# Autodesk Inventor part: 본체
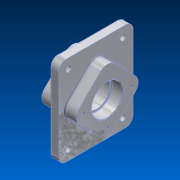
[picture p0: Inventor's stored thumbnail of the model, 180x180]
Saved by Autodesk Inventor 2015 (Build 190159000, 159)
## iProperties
Created: 2026-07
Part Number: 본체
Material: 알루미늄 6061
Document SubType Name: Modeling
Designer: user
Density: 2.7 g/cm^3
Appearance: 알루미늄 - 평지
Mass: 2132.41 g
Surface Area: 955.114 cm^2
Volume: 789.782 cm^3
Author: user
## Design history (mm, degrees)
sketch "스케치2"
  geometry: L1 (-75, 90)-(75, 90); L2 (75, 90)-(75, -90); L3 (75, -90)-(-75, -90); L4 (-75, -90)-(-75, 90); L5 (-75, 90)-(75, -90); L6 (75, 90)-(-75, -90); 1 further point
  constraints: 12 end point, 2 midpoint, 2 parallel, 1 horizontal, 1 perpendicular
  dimensions: "d0" = 150 distance of L2.end L3.end; "d1" = 180 distance of L1.end L2.end
extrude "돌출1" new body sketch "스케치2" stored distance "d2" = 18; taper "d3" = 0 deg
sketch "스케치3"
  geometry: L1 (70.711, 0)-(0, -70.711); L2 (0, -70.711)-(-70.711, 0); L3 (-70.711, 0)-(0, 70.711); L4 (0, 70.711)-(70.711, 0); 2 further points
  constraints: 8 end point, 1 coincident, 9 other
  dimensions: "d4" = 100 distance of L2.end L3.end
extrude "돌출2" join sketch "스케치3" distance "d5" = 23; taper "d6" = 0 deg
sketch "스케치4"
  geometry: L1 (-70.711, 0)-(0, 70.711); L2 (0, 70.711)-(70.711, 0); L3 (70.711, 0)-(0, -70.711); L4 (0, -70.711)-(-70.711, 0); 2 further points
  constraints: 8 end point, 1 coincident, 9 other
  dimensions: "d7" = 100 distance of L3.end L1.start
extrude "돌출3" join sketch "스케치4" distance "d8" = 29; taper "d9" = 0 deg
sketch "스케치5"
  geometry: L1 (0, 70.711)-(70.711, 0) reference; L2 (70.711, 0)-(0, -70.711) reference; L3 (0, -70.711)-(-70.711, 0) reference; L4 (-70.711, 0)-(0, 70.711) reference; L5 (-90, 75)-(90, 75) reference; L6 (90, 75)-(90, -75) reference; L7 (90, -75)-(-90, -75) reference; L8 (-90, -75)-(-90, 75) reference; C1 r 11 at (70, -55); C2 r 11 at (-70, -55); C3 r 11 at (70, 55); C4 r 11 at (-70, 55); 1 further point
  constraints: 4 centre point, 2 horizontal alignment, 1 vertical alignment
  dimensions: "d10" = 11 radius of C1; "d11" = 11 radius of C2; "d12" = 140 distance of C2.centre C1.centre; "d13" = 11 radius of C3; "d14" = 11 radius of C4; "d15" = 140 distance of C4.centre C3.centre; "d16" = 110 distance of C1.centre C3.centre; "d17" = 55 vertical distance of point (0, 0) C3.centre; "d18" = 70 horizontal distance of C4.centre point (0, 0)
extrude "돌출4" join sketch "스케치5" distance "d19" = 5; taper "d20" = 0 deg
hole "구멍1" diameter "d23" = 11; stored, may be unused: countersink angle "d27" = 90 deg, drill point angle "d29" = 0 deg; dims "d21" = 10, "d22" = 10, "d24" = 6, "d25" = 4, "d26" = 2, "d28" = 8
sketch "스케치6"
  geometry: C1 r 31 at (0, 0); 1 further point
  constraints: 1 centre point, 1 coincident
  dimensions: "d36" = 31 radius of C1
extrude "돌출5" cut sketch "스케치6" distance "d37" = 22; taper "d38" = 0 deg
sketch "스케치7"
  geometry: C1 r 31 at (0, 0); 1 further point
  constraints: 1 centre point, 1 coincident
  dimensions: "d39" = 31 radius of C1
extrude "돌출6" cut sketch "스케치7" distance "d40" = 22; taper "d41" = 0 deg
hole "구멍2" diameter "d44" = 54; stored, may be unused: countersink angle "d48" = 90 deg, drill point angle "d50" = 0 deg; dims "d42" = 10, "d43" = 10, "d45" = 6, "d46" = 4, "d47" = 2, "d49" = 8
sketch "스케치8"
  geometry: L1 (0, 0)-(-48, 0)
  constraints: 2 end point, 1 horizontal
  dimensions: "d51" = 48 distance of L1.start L1.end
hole "구멍3" sketch "스케치8" at (-48, 0) diameter "d52" = 4.917; stored, may be unused: countersink angle "d56" = 90 deg, drill point angle "d58" = 118 deg; dims "d53" = 10, "d54" = 4, "d55" = 2, "d57" = 13
sketch "스케치9"
  geometry: L1 (0, 0)-(48, 0); C1 r 2.458 at (48, 0) reference
  constraints: 2 end point, 1 horizontal
  dimensions: "d62" = 48 distance of L1.start L1.end (derived)
hole "구멍4" sketch "스케치9" at (48, 0) diameter "d63" = 4.917; stored, may be unused: countersink angle "d67" = 90 deg, drill point angle "d69" = 118 deg; dims "d64" = 10, "d65" = 4, "d66" = 2, "d68" = 13
sketch "스케치10"
  geometry: L1 (90, -75)-(90, 75) reference; 2 further points
  constraints: 1 horizontal alignment, 1 other
  dimensions: "d73" = 15 distance from line of point (75, 0) L1
feature "엠보싱1" sketch "스케치10" dims "d0" = 150, "d1" = 180, "d7" = 100, "d74" = 0.5, "d75" = 0
chamfer "모따기1" distance "d76" = 1; stored, may be unused: second distance "d77" = 2, angle "d78" = 45 deg
fillet "모깎기1" dims "d79" = 15
fillet "모깎기2" dims "d80" = 3
fillet "모깎기3" dims "d81" = 20
fillet "모깎기4" dims "d82" = 20
fillet "모깎기5" dims "d83" = 3
fillet "모깎기6" dims "d84" = 3
fillet "모깎기7" dims "d85" = 3
fillet "모깎기8" dims "d86" = 1
node "솔리드1"
pattern_linear "직사각형 패턴1" dims "d32" = 110
pattern_circular "원형 패턴1" dims angle "d60" = 360 deg
pattern_circular "원형 패턴2" dims angle "d71" = 360 deg
node "절단 모서리 투영1"
